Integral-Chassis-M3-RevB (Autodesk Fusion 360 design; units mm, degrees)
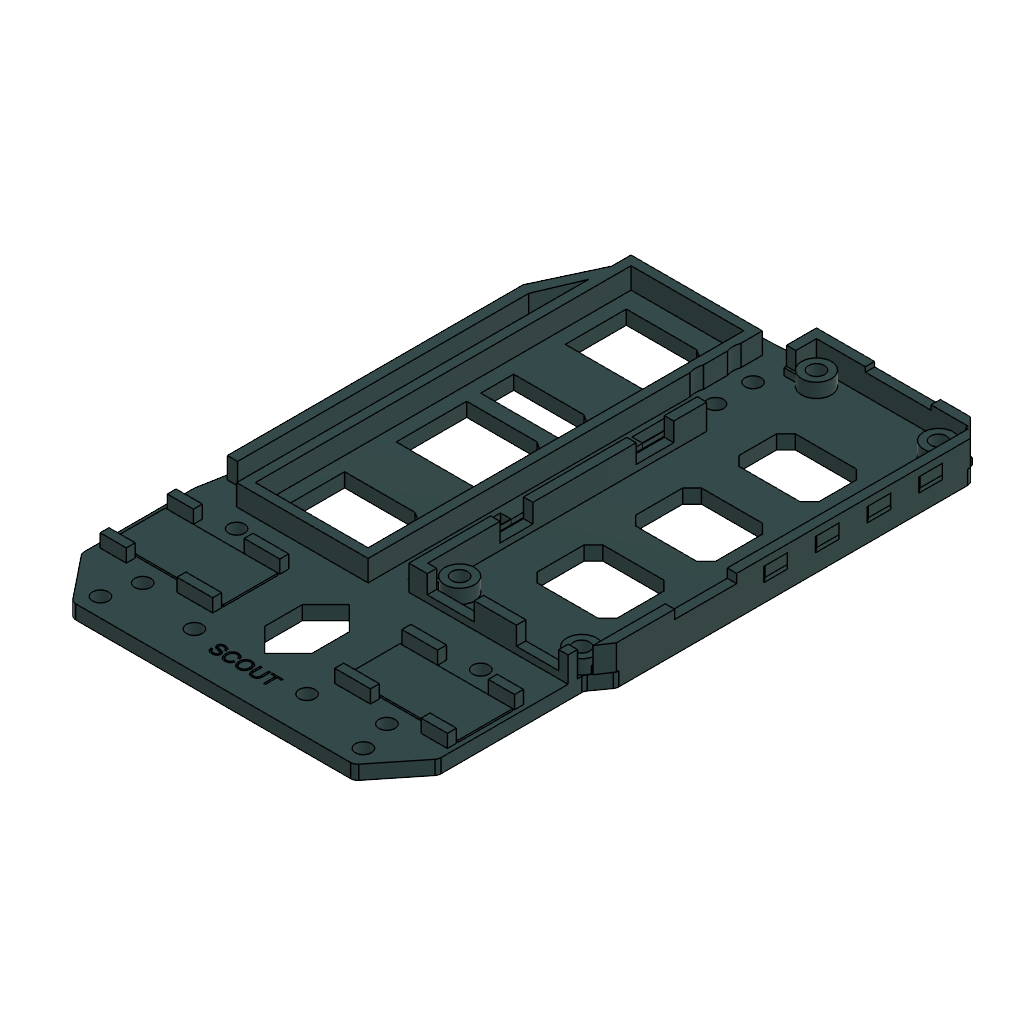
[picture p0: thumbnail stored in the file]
sketch "Continuous sculpted chassis floor outline" plane through (0, 0, 0) normal (0, 0, 1) x axis (1, 0, 0)
  line L1 (30, -53) -> (-30, -53)
  line L2 (38, -43) -> (30, -53)
  line L3 (38, -19) -> (38, -43)
  line L4 (38, -12) -> (38, -19)
  line L5 (40.9, -8) -> (38, -12)
  line L6 (40.9, 67.4) -> (40.9, -8)
  line L7 (36.9, 71.4) -> (40.9, 67.4)
  line L8 (-28, 68) -> (36.9, 71.4)
  line L9 (-36, 50) -> (-28, 68)
  line L10 (-36, -8) -> (-36, 50)
  line L11 (-38, -19) -> (-36, -8)
  line L12 (-38, -43) -> (-38, -19)
  line L13 (-30, -53) -> (-38, -43)
extrude "Extrude1" new body sketch "Continuous sculpted chassis floor outline" along normal blind 3
fillet "Fillet1" radius 1.5
sketch "Battery ladder window 1 outline" plane through (0, 0, 0) normal (0, 0, 1) x axis (1, 0, 0)
  line L1 (-7, -12) -> (-25, -12)
  line L2 (-7, -2) -> (-7, -12)
  line L3 (-10, 0) -> (-7, -2)
  line L4 (-25, 0) -> (-10, 0)
  line L5 (-25, -12) -> (-25, 0)
extrude "Extrude2" cut sketch "Battery ladder window 1 outline" along normal blind 3
sketch "Battery ladder window 2 outline" plane through (0, 0, 0) normal (0, 0, 1) x axis (1, 0, 0)
  line L1 (-7, 11) -> (-25, 11)
  line L2 (-7, 24) -> (-7, 11)
  line L3 (-10, 26) -> (-7, 24)
  line L4 (-25, 26) -> (-10, 26)
  line L5 (-25, 11) -> (-25, 26)
extrude "Extrude3" cut sketch "Battery ladder window 2 outline" along normal blind 3
sketch "Battery ladder window 3 outline" plane through (0, 0, 0) normal (0, 0, 1) x axis (1, 0, 0)
  line L1 (-7, 29) -> (-25, 29)
  line L2 (-7, 34) -> (-7, 29)
  line L3 (-10, 36) -> (-7, 34)
  line L4 (-25, 36) -> (-10, 36)
  line L5 (-25, 29) -> (-25, 36)
extrude "Extrude4" cut sketch "Battery ladder window 3 outline" along normal blind 3
sketch "Battery ladder window 4 outline" plane through (0, 0, 0) normal (0, 0, 1) x axis (1, 0, 0)
  line L1 (-7, 47) -> (-25, 47)
  line L2 (-7, 58) -> (-7, 47)
  line L3 (-10, 60) -> (-7, 58)
  line L4 (-25, 60) -> (-10, 60)
  line L5 (-25, 47) -> (-25, 60)
extrude "Extrude5" cut sketch "Battery ladder window 4 outline" along normal blind 3
sketch "Carrier service window 1 outline" plane through (0, 0, 0) normal (0, 0, 1) x axis (1, 0, 0)
  line L1 (29, 0) -> (16, 0)
  line L2 (31, 2) -> (29, 0)
  line L3 (31, 12) -> (31, 2)
  line L4 (29, 14) -> (31, 12)
  line L5 (16, 14) -> (29, 14)
  line L6 (14, 12) -> (16, 14)
  line L7 (14, 2) -> (14, 12)
  line L8 (16, 0) -> (14, 2)
extrude "Extrude6" cut sketch "Carrier service window 1 outline" along normal blind 3
sketch "Carrier service window 2 outline" plane through (0, 0, 0) normal (0, 0, 1) x axis (1, 0, 0)
  line L1 (29, 21) -> (16, 21)
  line L2 (31, 23) -> (29, 21)
  line L3 (31, 33) -> (31, 23)
  line L4 (29, 35) -> (31, 33)
  line L5 (16, 35) -> (29, 35)
  line L6 (14, 33) -> (16, 35)
  line L7 (14, 23) -> (14, 33)
  line L8 (16, 21) -> (14, 23)
extrude "Extrude7" cut sketch "Carrier service window 2 outline" along normal blind 3
sketch "Carrier service window 3 outline" plane through (0, 0, 0) normal (0, 0, 1) x axis (1, 0, 0)
  line L1 (29, 43) -> (16, 43)
  line L2 (31, 45) -> (29, 43)
  line L3 (31, 53) -> (31, 45)
  line L4 (29, 55) -> (31, 53)
  line L5 (16, 55) -> (29, 55)
  line L6 (14, 53) -> (16, 55)
  line L7 (14, 45) -> (14, 53)
  line L8 (16, 43) -> (14, 45)
extrude "Extrude8" cut sketch "Carrier service window 3 outline" along normal blind 3
work_plane "WorkPlane1" AlongDistance 3 ExtraOffset 0
sketch "Port sculpted rail outline" plane through (0, 0, 3) normal (0, 0, 1) x axis (1, 0, 0)
  line L1 (-36, -14) -> (-33.8, -14)
  line L2 (-36, 49) -> (-36, -14)
  line L3 (-29, 64) -> (-36, 49)
  line L4 (-27, 64) -> (-29, 64)
  line L5 (-33.8, 48) -> (-27, 64)
  line L6 (-33.8, -14) -> (-33.8, 48)
extrude "Extrude9" add sketch "Port sculpted rail outline" along normal blind 4.5
work_plane "WorkPlane2" AlongDistance 3 ExtraOffset 0
sketch "Battery cradle rails profiles" plane through (0, 0, 3) normal (0, 0, 1) x axis (1, 0, 0)
  line L1 (-28, -17) -> (-30, -17)
  line L2 (-28, 65) -> (-28, -17)
  line L3 (-30, 65) -> (-28, 65)
  line L4 (-30, -17) -> (-30, 65)
  line L5 (-2, -17) -> (-4, -17)
  line L6 (-2, 65) -> (-2, -17)
  line L7 (-4, 65) -> (-2, 65)
  line L8 (-4, -17) -> (-4, 65)
  line L9 (-2, -18) -> (-30, -18)
  line L10 (-2, -16) -> (-2, -18)
  line L11 (-30, -16) -> (-2, -16)
  line L12 (-30, -18) -> (-30, -16)
  line L13 (-2, 64) -> (-30, 64)
  line L14 (-2, 66) -> (-2, 64)
  line L15 (-30, 66) -> (-2, 66)
  line L16 (-30, 64) -> (-30, 66)
extrude "Extrude10" add sketch "Battery cradle rails profiles" along normal blind 4.5
work_plane "WorkPlane3" AlongDistance 3 ExtraOffset 0
sketch "Motor seating pads profiles" plane through (0, 0, 3) normal (0, 0, 1) x axis (1, 0, 0)
  line L1 (-13, -37.8) -> (-37, -37.8)
  line L2 (-13, -26.2) -> (-13, -37.8)
  line L3 (-37, -26.2) -> (-13, -26.2)
  line L4 (-37, -37.8) -> (-37, -26.2)
  line L5 (37, -37.8) -> (13, -37.8)
  line L6 (37, -26.2) -> (37, -37.8)
  line L7 (13, -26.2) -> (37, -26.2)
  line L8 (13, -37.8) -> (13, -26.2)
extrude "Extrude11" add sketch "Motor seating pads profiles" along normal blind 0.4
work_plane "WorkPlane4" AlongDistance 3 ExtraOffset 0
sketch "Motor locating fences profiles" plane through (0, 0, 3) normal (0, 0, 1) x axis (1, 0, 0)
  line L1 (-31.4, -40.1) -> (-37, -40.1)
  line L2 (-31.4, -38.2) -> (-31.4, -40.1)
  line L3 (-37, -38.2) -> (-31.4, -38.2)
  line L4 (-37, -40.1) -> (-37, -38.2)
  line L5 (-31.4, -25.8) -> (-37, -25.8)
  line L6 (-31.4, -23.9) -> (-31.4, -25.8)
  line L7 (-37, -23.9) -> (-31.4, -23.9)
  line L8 (-37, -25.8) -> (-37, -23.9)
  line L9 (-13, -40.1) -> (-20.6, -40.1)
  line L10 (-13, -38.2) -> (-13, -40.1)
  line L11 (-20.6, -38.2) -> (-13, -38.2)
  line L12 (-20.6, -40.1) -> (-20.6, -38.2)
  line L13 (-13, -25.8) -> (-20.6, -25.8)
  line L14 (-13, -23.9) -> (-13, -25.8)
  line L15 (-20.6, -23.9) -> (-13, -23.9)
  line L16 (-20.6, -25.8) -> (-20.6, -23.9)
  line L17 (20.6, -40.1) -> (13, -40.1)
  line L18 (20.6, -38.2) -> (20.6, -40.1)
  line L19 (13, -38.2) -> (20.6, -38.2)
  line L20 (13, -40.1) -> (13, -38.2)
  line L21 (20.6, -25.8) -> (13, -25.8)
  line L22 (20.6, -23.9) -> (20.6, -25.8)
  line L23 (13, -23.9) -> (20.6, -23.9)
  line L24 (13, -25.8) -> (13, -23.9)
  line L25 (37, -40.1) -> (31.4, -40.1)
  line L26 (37, -38.2) -> (37, -40.1)
  line L27 (31.4, -38.2) -> (37, -38.2)
  line L28 (31.4, -40.1) -> (31.4, -38.2)
  line L29 (37, -25.8) -> (31.4, -25.8)
  line L30 (37, -23.9) -> (37, -25.8)
  line L31 (31.4, -23.9) -> (37, -23.9)
  line L32 (31.4, -25.8) -> (31.4, -23.9)
extrude "Extrude12" add sketch "Motor locating fences profiles" along normal blind 2.8
sketch "Battery strap passages profiles" plane through (0, 0, 0) normal (0, 0, 1) x axis (1, 0, 0)
  line L1 (-30.8, 1) -> (-33, 1)
  line L2 (-30.8, 9) -> (-30.8, 1)
  line L3 (-33, 9) -> (-30.8, 9)
  line L4 (-33, 1) -> (-33, 9)
  line L5 (-30.8, 37) -> (-33, 37)
  line L6 (-30.8, 45) -> (-30.8, 37)
  line L7 (-33, 45) -> (-30.8, 45)
  line L8 (-33, 37) -> (-33, 45)
  line L9 (1.4, 1) -> (-0.8, 1)
  line L10 (1.4, 9) -> (1.4, 1)
  line L11 (-0.8, 9) -> (1.4, 9)
  line L12 (-0.8, 1) -> (-0.8, 9)
  line L13 (1.4, 37) -> (-0.8, 37)
  line L14 (1.4, 45) -> (1.4, 37)
  line L15 (-0.8, 45) -> (1.4, 45)
  line L16 (-0.8, 37) -> (-0.8, 45)
extrude "Extrude13" cut sketch "Battery strap passages profiles" along normal blind 3
sketch "All chassis M3 clearances profile" plane through (0, 0, 0) normal (0, 0, 1) x axis (1, 0, 0)
  circle C1 centre (-26, -42) radius 1.7
  circle C2 centre (-26, -22) radius 1.7
  circle C3 centre (26, -42) radius 1.7
  circle C4 centre (26, -22) radius 1.7
  circle C5 centre (-28, -49) radius 1.7
  circle C6 centre (28, -49) radius 1.7
  circle C7 centre (2, 52) radius 1.7
  circle C8 centre (2, 60) radius 1.7
  circle C9 centre (-12, -45) radius 1.7
  circle C10 centre (12, -45) radius 1.7
extrude "Extrude14" cut sketch "All chassis M3 clearances profile" along normal blind 3
sketch "Front diamond opening outline" plane through (0, 0, 0) normal (0, 0, 1) x axis (1, 0, 0)
  line L1 (0, -42) -> (-5, -37)
  line L2 (5, -37) -> (0, -42)
  line L3 (5, -29) -> (5, -37)
  line L4 (0, -24) -> (5, -29)
  line L5 (-5, -29) -> (0, -24)
  line L6 (-5, -37) -> (-5, -29)
extrude "Extrude15" cut sketch "Front diamond opening outline" along normal blind 3
work_plane "WorkPlane5" AlongDistance 3 ExtraOffset 0
sketch "Carrier locating walls profiles" plane through (0, 0, 3) normal (0, 0, 1) x axis (1, 0, 0)
  line L1 (38, -15.4) -> (4.1, -15.4)
  line L2 (38, -13.4) -> (38, -15.4)
  line L3 (4.1, -13.4) -> (38, -13.4)
  line L4 (4.1, -15.4) -> (4.1, -13.4)
  line L5 (6.1, -13.4) -> (4.1, -13.4)
  line L6 (6.1, 46) -> (6.1, -13.4)
  line L7 (4.1, 46) -> (6.1, 46)
  line L8 (4.1, -13.4) -> (4.1, 46)
  line L9 (6.1, 65) -> (4.1, 65)
  line L10 (6.1, 69.4) -> (6.1, 65)
  line L11 (4.1, 69.4) -> (6.1, 69.4)
  line L12 (4.1, 65) -> (4.1, 69.4)
  line L13 (38.9, 69.4) -> (4.1, 69.4)
  line L14 (38.9, 71.4) -> (38.9, 69.4)
  line L15 (4.1, 71.4) -> (38.9, 71.4)
  line L16 (4.1, 69.4) -> (4.1, 71.4)
extrude "Extrude16" add sketch "Carrier locating walls profiles" along normal blind 5.4
work_plane "WorkPlane6" AlongDistance 3 ExtraOffset 0
sketch "Swept starboard bay wall outline" plane through (0, 0, 3) normal (0, 0, 1) x axis (1, 0, 0)
  line L1 (40.9, -8) -> (38.9, -11)
  line L2 (40.9, 67.4) -> (40.9, -8)
  line L3 (38.9, 69.4) -> (40.9, 67.4)
  line L4 (38.9, -11) -> (38.9, 69.4)
extrude "Extrude17" add sketch "Swept starboard bay wall outline" along normal blind 5.4
work_plane "WorkPlane7" AlongDistance 3 ExtraOffset 0
sketch "Four integral corner seats" plane through (0, 0, 3) normal (0, 0, 1) x axis (1, 0, 0)
  circle C1 centre (9.5, -10) radius 3.2
  circle C2 centre (35.5, -10) radius 3.2
  circle C3 centre (9.5, 66) radius 3.2
  circle C4 centre (35.5, 66) radius 3.2
extrude "Extrude18" add sketch "Four integral corner seats" along normal blind 3
work_plane "WorkPlane8" AlongDistance 3 ExtraOffset 0
sketch "Corner seat buttresses profiles" plane through (0, 0, 3) normal (0, 0, 1) x axis (1, 0, 0)
  line L1 (9.5, -12) -> (4.1, -12)
  line L2 (9.5, -8) -> (9.5, -12)
  line L3 (4.1, -8) -> (9.5, -8)
  line L4 (4.1, -12) -> (4.1, -8)
  line L5 (38.7, -11) -> (35.5, -11)
  line L6 (38.7, -8) -> (38.7, -11)
  line L7 (35.5, -8) -> (38.7, -8)
  line L8 (35.5, -11) -> (35.5, -8)
  line L9 (9.5, 64.5) -> (4.1, 64.5)
  line L10 (9.5, 68) -> (9.5, 64.5)
  line L11 (4.1, 68) -> (9.5, 68)
  line L12 (4.1, 64.5) -> (4.1, 68)
  line L13 (40.7, 64) -> (35.5, 64)
  line L14 (40.7, 68) -> (40.7, 64)
  line L15 (35.5, 68) -> (40.7, 68)
  line L16 (35.5, 64) -> (35.5, 68)
extrude "Extrude19" add sketch "Corner seat buttresses profiles" along normal blind 1.5
sketch "Carrier M3 clearance bores profile" plane through (0, 0, 0) normal (0, 0, 1) x axis (1, 0, 0)
  circle C1 centre (9.5, -10) radius 1.7
  circle C2 centre (35.5, -10) radius 1.7
  circle C3 centre (9.5, 66) radius 1.7
  circle C4 centre (35.5, 66) radius 1.7
extrude "Extrude20" cut sketch "Carrier M3 clearance bores profile" along normal blind 6
sketch "Underside M3 captive nut pockets profiles" plane through (0, 0, 0) normal (0, 0, 1) x axis (1, 0, 0)
  line L1 (11.1743, -7.1) -> (12.8486, -10)
  line L2 (7.8257, -7.1) -> (11.1743, -7.1)
  line L3 (6.1514, -10) -> (7.8257, -7.1)
  line L4 (7.8257, -12.9) -> (6.1514, -10)
  line L5 (11.1743, -12.9) -> (7.8257, -12.9)
  line L6 (12.8486, -10) -> (11.1743, -12.9)
  line L7 (37.1743, -7.1) -> (38.8486, -10)
  line L8 (33.8257, -7.1) -> (37.1743, -7.1)
  line L9 (32.1514, -10) -> (33.8257, -7.1)
  line L10 (33.8257, -12.9) -> (32.1514, -10)
  line L11 (37.1743, -12.9) -> (33.8257, -12.9)
  line L12 (38.8486, -10) -> (37.1743, -12.9)
  line L13 (11.1743, 68.9) -> (12.8486, 66)
  line L14 (7.8257, 68.9) -> (11.1743, 68.9)
  line L15 (6.1514, 66) -> (7.8257, 68.9)
  line L16 (7.8257, 63.1) -> (6.1514, 66)
  line L17 (11.1743, 63.1) -> (7.8257, 63.1)
  line L18 (12.8486, 66) -> (11.1743, 63.1)
  line L19 (37.1743, 68.9) -> (38.8486, 66)
  line L20 (33.8257, 68.9) -> (37.1743, 68.9)
  line L21 (32.1514, 66) -> (33.8257, 68.9)
  line L22 (33.8257, 63.1) -> (32.1514, 66)
  line L23 (37.1743, 63.1) -> (33.8257, 63.1)
  line L24 (38.8486, 66) -> (37.1743, 63.1)
extrude "Extrude21" cut sketch "Underside M3 captive nut pockets profiles" along normal blind 2.6
work_plane "WorkPlane9" AlongDistance 6.5 ExtraOffset 0
sketch "USB C side plug opening profile" plane through (0, 0, 6.5) normal (0, 0, 1) x axis (1, 0, 0)
  line L1 (42, 4.4) -> (38.8, 4.4)
  line L2 (42, 17.6) -> (42, 4.4)
  line L3 (38.8, 17.6) -> (42, 17.6)
  line L4 (38.8, 4.4) -> (38.8, 17.6)
extrude "Extrude22" cut sketch "USB C side plug opening profile" along normal blind 3
work_plane "WorkPlane10" AlongDistance 7.4 ExtraOffset 0
sketch "Programming USB rear scallop profile" plane through (0, 0, 7.4) normal (0, 0, 1) x axis (1, 0, 0)
  line L1 (30.5, 69.2) -> (16.5, 69.2)
  line L2 (30.5, 71.6) -> (30.5, 69.2)
  line L3 (16.5, 71.6) -> (30.5, 71.6)
  line L4 (16.5, 69.2) -> (16.5, 71.6)
extrude "Extrude23" cut sketch "Programming USB rear scallop profile" along normal blind 1.2
work_plane "WorkPlane11" AlongDistance 4.5 ExtraOffset 0
sketch "Motor wire exits profiles" plane through (0, 0, 4.5) normal (0, 0, 1) x axis (1, 0, 0)
  line L1 (18, -15.6) -> (8, -15.6)
  line L2 (18, -13.2) -> (18, -15.6)
  line L3 (8, -13.2) -> (18, -13.2)
  line L4 (8, -15.6) -> (8, -13.2)
  line L5 (36, -15.6) -> (27, -15.6)
  line L6 (36, -13.2) -> (36, -15.6)
  line L7 (27, -13.2) -> (36, -13.2)
  line L8 (27, -15.6) -> (27, -13.2)
extrude "Extrude24" cut sketch "Motor wire exits profiles" along normal blind 4
work_plane "WorkPlane12" AlongDistance 4.4 ExtraOffset 0
sketch "Battery and RUN wire exits profiles" plane through (0, 0, 4.4) normal (0, 0, 1) x axis (1, 0, 0)
  line L1 (6.3, 2) -> (3.9, 2)
  line L2 (6.3, 9) -> (6.3, 2)
  line L3 (3.9, 9) -> (6.3, 9)
  line L4 (3.9, 2) -> (3.9, 9)
  line L5 (6.3, 31) -> (3.9, 31)
  line L6 (6.3, 39) -> (6.3, 31)
  line L7 (3.9, 39) -> (6.3, 39)
  line L8 (3.9, 31) -> (3.9, 39)
extrude "Extrude25" cut sketch "Battery and RUN wire exits profiles" along normal blind 4.2
work_plane "WorkPlane13" AlongDistance 2 ExtraOffset 0
sketch "Central recessed wire channel profile" plane through (0, 0, 2) normal (0, 0, 1) x axis (1, 0, 0)
  line L1 (3.6, -13) -> (1.5, -13)
  line L2 (3.6, 46) -> (3.6, -13)
  line L3 (1.5, 46) -> (3.6, 46)
  line L4 (1.5, -13) -> (1.5, 46)
extrude "Extrude26" cut sketch "Central recessed wire channel profile" along normal blind 1
work_plane "WorkPlane14" AlongDistance 3 ExtraOffset 0
sketch "Tail screw driver access relief profile" plane through (0, 0, 3) normal (0, 0, 1) x axis (1, 0, 0)
  circle C1 centre (2, 52) radius 4.25
  circle C2 centre (2, 60) radius 4.25
extrude "Extrude27" cut sketch "Tail screw driver access relief profile" along normal blind 6
work_plane "WorkPlane15" AlongDistance 3.8 ExtraOffset 0
sketch "Starboard sculpted gill 1 outline" plane through (0, 0, 3.8) normal (0, 0, 1) x axis (1, 0, 0)
  line L1 (41.2, 23) -> (40.05, 24.5)
  line L2 (41.2, 28) -> (41.2, 23)
  line L3 (40.05, 29.5) -> (41.2, 28)
  line L4 (40.05, 24.5) -> (40.05, 29.5)
extrude "Extrude28" cut sketch "Starboard sculpted gill 1 outline" along normal blind 3
work_plane "WorkPlane16" AlongDistance 3.8 ExtraOffset 0
sketch "Starboard sculpted gill 2 outline" plane through (0, 0, 3.8) normal (0, 0, 1) x axis (1, 0, 0)
  line L1 (41.2, 34) -> (40.05, 35.5)
  line L2 (41.2, 39) -> (41.2, 34)
  line L3 (40.05, 40.5) -> (41.2, 39)
  line L4 (40.05, 35.5) -> (40.05, 40.5)
extrude "Extrude29" cut sketch "Starboard sculpted gill 2 outline" along normal blind 3
work_plane "WorkPlane17" AlongDistance 3.8 ExtraOffset 0
sketch "Starboard sculpted gill 3 outline" plane through (0, 0, 3.8) normal (0, 0, 1) x axis (1, 0, 0)
  line L1 (41.2, 45) -> (40.05, 46.5)
  line L2 (41.2, 50) -> (41.2, 45)
  line L3 (40.05, 51.5) -> (41.2, 50)
  line L4 (40.05, 46.5) -> (40.05, 51.5)
extrude "Extrude30" cut sketch "Starboard sculpted gill 3 outline" along normal blind 3
work_plane "WorkPlane18" AlongDistance 3.8 ExtraOffset 0
sketch "Starboard sculpted gill 4 outline" plane through (0, 0, 3.8) normal (0, 0, 1) x axis (1, 0, 0)
  line L1 (41.2, 56) -> (40.05, 57.5)
  line L2 (41.2, 61) -> (41.2, 56)
  line L3 (40.05, 62.5) -> (41.2, 61)
  line L4 (40.05, 57.5) -> (40.05, 62.5)
extrude "Extrude31" cut sketch "Starboard sculpted gill 4 outline" along normal blind 3
work_plane "WorkPlane19" AlongDistance 3 ExtraOffset 0
sketch "SCOUT marking" plane through (0, 0, 3) normal (0, 0, 1) x axis (1, 0, 0)
  dimension "d1488" = 2.8
extrude "Extrude32" cut sketch "SCOUT marking" against normal blind 0.35
sketch "Rear bay floor continuous print support outline" plane through (0, 0, 0) normal (0, 0, 1) x axis (1, 0, 0)
  line L1 (36.9, 70.9) -> (3.8, 69)
  line L2 (36.9, 71.4) -> (36.9, 70.9)
  line L3 (4.1, 71.4) -> (36.9, 71.4)
  line L4 (3.8, 71.1) -> (4.1, 71.4)
  line L5 (3.8, 69) -> (3.8, 71.1)
extrude "Extrude33" add sketch "Rear bay floor continuous print support outline" along normal blind 3
work_plane "WorkPlane20" AlongDistance 3 ExtraOffset 0
sketch "Rear wall follows chassis bevel outline" plane through (0, 0, 3) normal (0, 0, 1) x axis (1, 0, 0)
  line L1 (39.1, 69.4) -> (38.9, 69.4)
  line L2 (39.1, 71.6) -> (39.1, 69.4)
  line L3 (36.7, 71.6) -> (39.1, 71.6)
  line L4 (38.9, 69.4) -> (36.7, 71.6)
extrude "Extrude34" cut sketch "Rear wall follows chassis bevel outline" along normal blind 6
work_plane "WorkPlane21" AlongDistance 3 ExtraOffset 0
sketch "Open battery holder well profile" plane through (0, 0, 3) normal (0, 0, 1) x axis (1, 0, 0)
  line L1 (-4, -16) -> (-28, -16)
  line L2 (-4, 64) -> (-4, -16)
  line L3 (-28, 64) -> (-4, 64)
  line L4 (-28, -16) -> (-28, 64)
extrude "Extrude35" cut sketch "Open battery holder well profile" along normal blind 4.5
work_plane "WorkPlane22" AlongDistance 3 ExtraOffset 0
sketch "Continuous rear corner web outline" plane through (0, 0, 3) normal (0, 0, 1) x axis (1, 0, 0)
  line L1 (39.4, 68.9) -> (38.4, 68.9)
  line L2 (38.4, 69.9) -> (39.4, 68.9)
  line L3 (38.4, 68.9) -> (38.4, 69.9)
extrude "Extrude36" add sketch "Continuous rear corner web outline" along normal blind 5.4
named bodies: "Integral chassis and carrier bay"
